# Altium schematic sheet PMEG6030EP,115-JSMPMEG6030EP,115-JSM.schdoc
size 127 x 101 mm
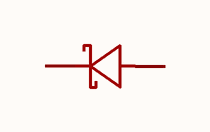
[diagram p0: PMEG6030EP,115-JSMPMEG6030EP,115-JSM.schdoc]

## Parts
D?  pmeg6030ep,115-jsm  [SOD-128_L3.4-W2.6-LS4.6-RD]  (value not drawn)

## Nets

Not connected (* = marked no-connect by the designer): D? 1(C) 2(A)

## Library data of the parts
D? = pmeg6030ep,115-jsm: 二极管配置:1个独立式;正向压降(Vf):700mV@2A;直流反向耐压(Vr):60V;整流电流:3A;; Manufacturer: JSMSEMI(杰盛微); AddInBom: yes; ModelId: 7822c0923f374c74aacdf298ebca7d16; ModelTransform: 181.102,102.362,0,0,0,0,0,0,0; Diode Configuration: 1个独立式; Voltage - DC Reverse(Vr): 60V; Current - Rectified: 3A; Reverse Leakage Current (Ir): 100uA@60V; Operating Junction Temperature Range: -55℃~+150℃; Non-Repetitive Peak Forward Surge Current: 50A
